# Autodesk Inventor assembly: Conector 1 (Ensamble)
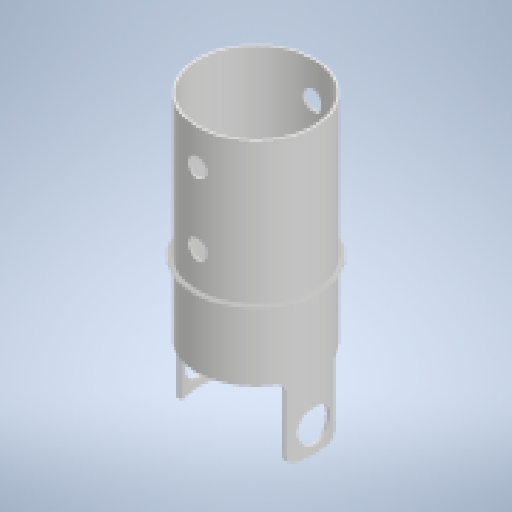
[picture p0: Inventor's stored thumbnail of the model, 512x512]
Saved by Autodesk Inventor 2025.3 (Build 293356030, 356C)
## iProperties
Created: 2025-10
Part Number: Conector 1 (Ensamble)
Document SubType Name: Assembly
Designer: Asus
Author: Asus
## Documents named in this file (4)
- C:\Users\User\Downloads\Anclaje 3\Conector a Guadua (Ensamble).iam
- C:\Users\User\Downloads\Anclaje 3\Tuberia Interior.ipt
- C:\Users\User\Downloads\Anclaje 3\Disco Soporte.ipt
- C:\Users\User\Downloads\Anclaje 3\Tuberia Conector 1.ipt
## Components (3 placed, 3 different names)
1. Tuberia Interior:1 — Nivelación:1, Nivelación:2, Coincidencia:1, Coincidencia:2, Coincidencia:4, Coincidencia:6
2. Disco Soporte:1 — Coincidencia:2, Nivelación:3, Coincidencia:3, Coincidencia:4, Coincidencia:5
3. Tuberia Conector 1:1 — Coincidencia:5, Coincidencia:6, Nivelación:4
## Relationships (10: Mate 6, Flush 4)
- Nivelación:1 [Flush]: Tuberia Interior:1
- Nivelación:2 [Flush]: Tuberia Interior:1
- Coincidencia:1 [Mate]: Tuberia Interior:1
- Coincidencia:2 [Mate]: Tuberia Interior:1 ↔ Disco Soporte:1
- Nivelación:3 [Flush]: Disco Soporte:1
- Coincidencia:3 [Mate]: Disco Soporte:1
- Coincidencia:4 [Mate]: Tuberia Interior:1 ↔ Disco Soporte:1
- Coincidencia:5 [Mate]: Disco Soporte:1 ↔ Tuberia Conector 1:1
- Coincidencia:6 [Mate]: Tuberia Interior:1 ↔ Tuberia Conector 1:1
- Nivelación:4 [Flush]: Tuberia Conector 1:1
